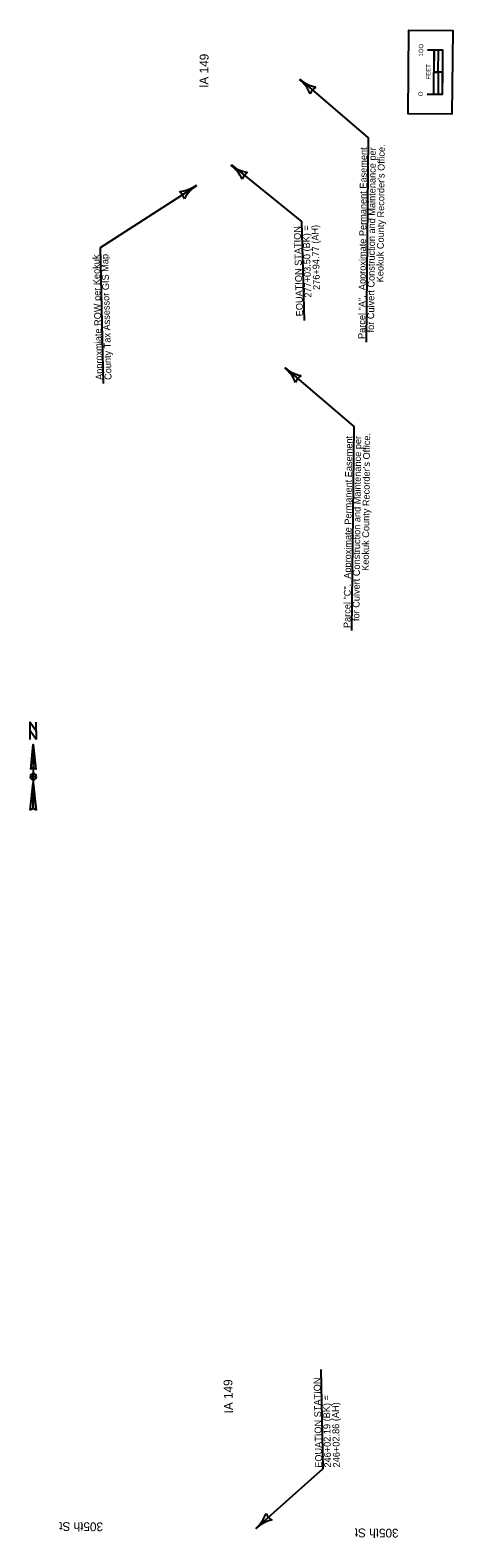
# Model space of a CAD drawing. Extents: x 23417754 to 23421386, y 6737896 to 6790956.
# Drawn here: x 23417754 to 23418715, y 6751055 to 6754484 of the extents above; entities that cross this region are included whole.
import ezdxf

# ---------------------------------------------------------------- set-up
doc = ezdxf.new("R2010")
doc.units = 0
for name, color, linetype in [('Curb', 7, 'Continuous'), ('Default', 7, 'Continuous'), ('dsnCellElements', 7, 'Continuous'), ('RasterAttachment', 7, 'Continuous'), ('TextAlignmentLrg', 7, 'Continuous')]:
    doc.layers.add(name, color=color, linetype=linetype)

msp = doc.modelspace()

# ---------------------------------------------------------------- linework, layer by layer
at = {"layer": 'Curb'}
msp.add_line((23418692.2, 6754388.6), (23418672.2, 6754388.8), dxfattribs=at)
msp.add_line((23418692.2, 6754388.6), (23418672.2, 6754388.8), dxfattribs=at)
for points in [[(23418613.2, 6754294.4), (23418615.2, 6754484.4), (23418715.2, 6754483.3), (23418713.2, 6754293.3)], [(23418713.2, 6754293.3), (23418613.2, 6754294.4), (23418615.2, 6754484.4), (23418715.2, 6754483.3)], [(23418682.2, 6754388.7), (23418682.7, 6754438.7), (23418672.8, 6754438.8), (23418672.2, 6754388.8)], [(23418691.7, 6754338.6), (23418692.2, 6754388.6), (23418682.2, 6754388.7), (23418681.6, 6754338.7)]]:
    msp.add_lwpolyline(points, close=True, dxfattribs=at)
for points in [[(23418656.7, 6754338.9), (23418691.7, 6754338.6), (23418692.8, 6754438.6), (23418657.8, 6754438.9)], [(23418671.7, 6754338.8), (23418672.8, 6754438.8)]]:
    msp.add_lwpolyline(points, dxfattribs=at)
at = {"layer": 'dsnCellElements'}
for points in [[(23418367.3, 6754372.8), (23418522.9, 6754239.5), (23418518, 6753775.1)], [(23418211.4, 6754177.7), (23418370.7, 6754048.9), (23418376.7, 6753823.7)], [(23418131.7, 6754130.2), (23417912.6, 6753989.3), (23417919.3, 6753680.4)], [(23418334, 6753716.4), (23418489.6, 6753583.2), (23418484.7, 6753118.7)], [(23418267.3, 6751076.8), (23418420.3, 6751213.1), (23418415.6, 6751438.3)]]:
    msp.add_lwpolyline(points, dxfattribs=at)
for centre, radius, start, end in [((23418419.5, 6754438.6), 85, 231.0009, 259.0734), ((23418312.5, 6754306.4), 85, 22.9284, 51.0009), ((23418421.4, 6754327.6), 32.8, 123.2676, 158.7343), ((23418261.7, 6754245), 85, 232.5974, 260.6699), ((23418158.5, 6754109.9), 85, 24.5249, 52.5974), ((23418266.7, 6754134.1), 32.8, 124.8641, 160.3308), ((23418083.9, 6754201.8), 85, 276.2476, 304.3201), ((23418179.8, 6754061.3), 85, 124.3201, 152.3926), ((23418072.9, 6754091.4), 32.8, 16.5868, 52.0535), ((23418386.2, 6753782.2), 85, 231.0009, 259.0734), ((23418279.2, 6753650.1), 85, 22.9284, 51.0009), ((23418388.1, 6753671.3), 32.8, 123.2676, 158.7343), ((23418210.7, 6751140.3), 85, 311.7029, 339.7753), ((23418320.5, 6751124.2), 32.8, 203.9695, 239.4362), ((23418323.9, 6751013.3), 85, 103.6304, 131.7029)]:
    msp.add_arc(centre, radius, start, end, dxfattribs=at)
at = {"layer": 'TextAlignmentLrg'}
for p, q in [((23417760.6, 6752859.5), (23417766.2, 6752803.1)), ((23417760.6, 6752859.5), (23417760.6, 6752713)), ((23417754.9, 6752803.1), (23417754.9, 6752803.1)), ((23417755.2, 6752803.6), (23417756.2, 6752804.8)), ((23417753.5, 6752710.2), (23417760.6, 6752772.1)), ((23417760.6, 6752779.2), (23417760.6, 6752779.2))]:
    msp.add_line(p, q, dxfattribs=at)
msp.add_lwpolyline([(23417767.6, 6752870.7), (23417753.5, 6752890.5), (23417753.5, 6752910.2), (23417767.6, 6752890.5)], close=True, dxfattribs=at)
for points in [[(23417753.5, 6752870.7), (23417753.5, 6752910.2), (23417767.6, 6752890.5), (23417767.6, 6752910.2)], [(23417754.9, 6752803.1), (23417760.6, 6752859.5), (23417760.6, 6752805.9)], [(23417767.6, 6752786.2), (23417760.6, 6752786.2), (23417760.6, 6752793.3)], [(23417760.6, 6752779.2), (23417760.6, 6752786.2), (23417753.5, 6752786.2)], [(23417760.6, 6752713), (23417760.6, 6752772.1), (23417767.6, 6752710.2)]]:
    msp.add_lwpolyline(points, dxfattribs=at)
for centre, radius, start, end in [((23417760.6, 6752786.2), 7.04, 90, 180), ((23417760.6, 6752798.9), 7.04, 90.0204, 143.1257), ((23417760.6, 6752798.9), 7.04, 36.8481, 90.0218), ((23417760.6, 6752786.2), 7.04, 0, 90), ((23417760.6, 6752786.2), 7.04, 180, 270), ((23417760.6, 6752786.2), 7.04, 270, 360), ((23417760.6, 6752702.8), 10.2, 89.9894, 133.619), ((23417760.6, 6752702.8), 10.2, 46.4021, 90.0006)]:
    msp.add_arc(centre, radius, start, end, dxfattribs=at)

# ---------------------------------------------------------------- texts
at = {"layer": 'Curb'}
for s, p in [('1OO', (23418647.6, 6754424.2)), ('1OO', (23418647.6, 6754424.2)), ('FEET', (23418664.1, 6754371.9)), ('O', (23418646.7, 6754334.1)), ('O', (23418646.7, 6754334.1))]:
    msp.add_text(s, height=10, rotation=89.3974, dxfattribs=at).set_placement(p)
at = {"layer": 'Default'}
for rotation, p in [(89.3974, (23418158.7, 6754353.2)), (91.1771, (23418215.1, 6751338.5))]:
    msp.add_text('IA 149', height=20, rotation=rotation, dxfattribs=at).set_placement(p)
at = {"layer": 'dsnCellElements'}
for s, rotation, p in [('Parcel "A".  Approximate Permanent Easement', 89.3974, (23418515.5, 6753781.9)), ('for Culvert Construction and Maintenance per', 89.3974, (23418535.8, 6753796.8)), ("Keokuk County Recorder's Office.", 89.3974, (23418557.2, 6753910.9)), ('EQUATION STATION', 91.5477, (23418374.4, 6753833.8)), ('277+03.50 (BK) = ', 91.5477, (23418393.4, 6753876.2)), ('276+94.77 (AH)', 91.5477, (23418413.1, 6753893.8)), ('Approxmiate ROW per Keokuk', 91.5477, (23417918.6, 6753689)), ('County Tax Assessor GIS Map', 91.5477, (23417938.8, 6753689.1)), ('Parcel "C".  Approximate Permanent Easement', 89.3974, (23418482.1, 6753124.4)), ('for Culvert Construction and Maintenance per', 89.3974, (23418502.5, 6753140.4)), ("Keokuk County Recorder's Office.", 89.3974, (23418523.9, 6753254.5)), ('EQUATION STATION', 91.1772, (23418418.1, 6751214.8)), ('246+02.19 (BK) = ', 91.1772, (23418438.3, 6751215.3)), ('246+02.86 (AH)', 91.1772, (23418458.5, 6751215.7))]:
    msp.add_text(s, height=15.605, rotation=rotation, dxfattribs=at).set_placement(p)
at = {"layer": 'RasterAttachment'}
for p in [(23417919.4, 6751090.3), (23418591.8, 6751075.9)]:
    msp.add_text('305th St', height=20, rotation=179.5786, dxfattribs=at).set_placement(p)

doc.saveas('drawing.dxf')
